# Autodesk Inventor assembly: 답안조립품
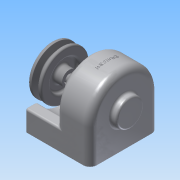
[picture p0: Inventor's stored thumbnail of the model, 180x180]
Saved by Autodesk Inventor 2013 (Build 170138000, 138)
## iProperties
Created: 2015-02
Part Number: 답안조립품
Document SubType Name: Assembly
Designer: Administrator
Author: Administrator
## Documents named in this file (14)
- C:\Documents and Settings\Administrator\바탕 화면\450214V1007\답안조립품.iam
- C:\Documents and Settings\Administrator\바탕 화면\450214V1007\1-본체.ipt
- C:\Documents and Settings\Administrator\바탕 화면\450214V1007\베어링 6001.ipt
- C:\Documents and Settings\Administrator\바탕 화면\450214V1007\축.ipt
- C:\Documents and Settings\Administrator\바탕 화면\450214V1007\키5x5.ipt
- C:\Documents and Settings\Administrator\바탕 화면\450214V1007\스퍼기어.ipt
- C:\Documents and Settings\Administrator\바탕 화면\450214V1007\축커버.ipt
- C:\Documents and Settings\Administrator\바탕 화면\450214V1007\키4x4.ipt
- C:\Documents and Settings\Administrator\바탕 화면\450214V1007\M3x0.5.ipt
- C:\Documents and Settings\Administrator\바탕 화면\450214V1007\오일실.ipt
- C:\Documents and Settings\Administrator\바탕 화면\450214V1007\4-벨트풀리.ipt
- C:\Documents and Settings\Administrator\바탕 화면\450214V1007\M5x0.8.ipt
- M5x0.8.ipt
- C:\Documents and Settings\Administrator\바탕 화면\450214V1007\와샤.ipt
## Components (7 placed, 4 different names)
1. 1-본체:1
2. 4-벨트풀리:1 — 각도:4
3. M5x0.8:1 — 각도:5
4. M3x0.5:1
5. M3x0.5:2
6. M3x0.5:3
7. M3x0.5:4
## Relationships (2: Angle 2)
- 각도:4 [Angle]: 4-벨트풀리:1
- 각도:5 [Angle]: M5x0.8:1
